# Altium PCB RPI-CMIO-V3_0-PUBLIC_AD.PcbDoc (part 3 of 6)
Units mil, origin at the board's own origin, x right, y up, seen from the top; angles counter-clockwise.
Board outline 3295.4 x 4105.44 mil, 6 copper layers (TOP, GNDT, PWRT, PWRB, GNDB, BOTTOM); 114 components, 152 nets, 703 pads, 476 vias.
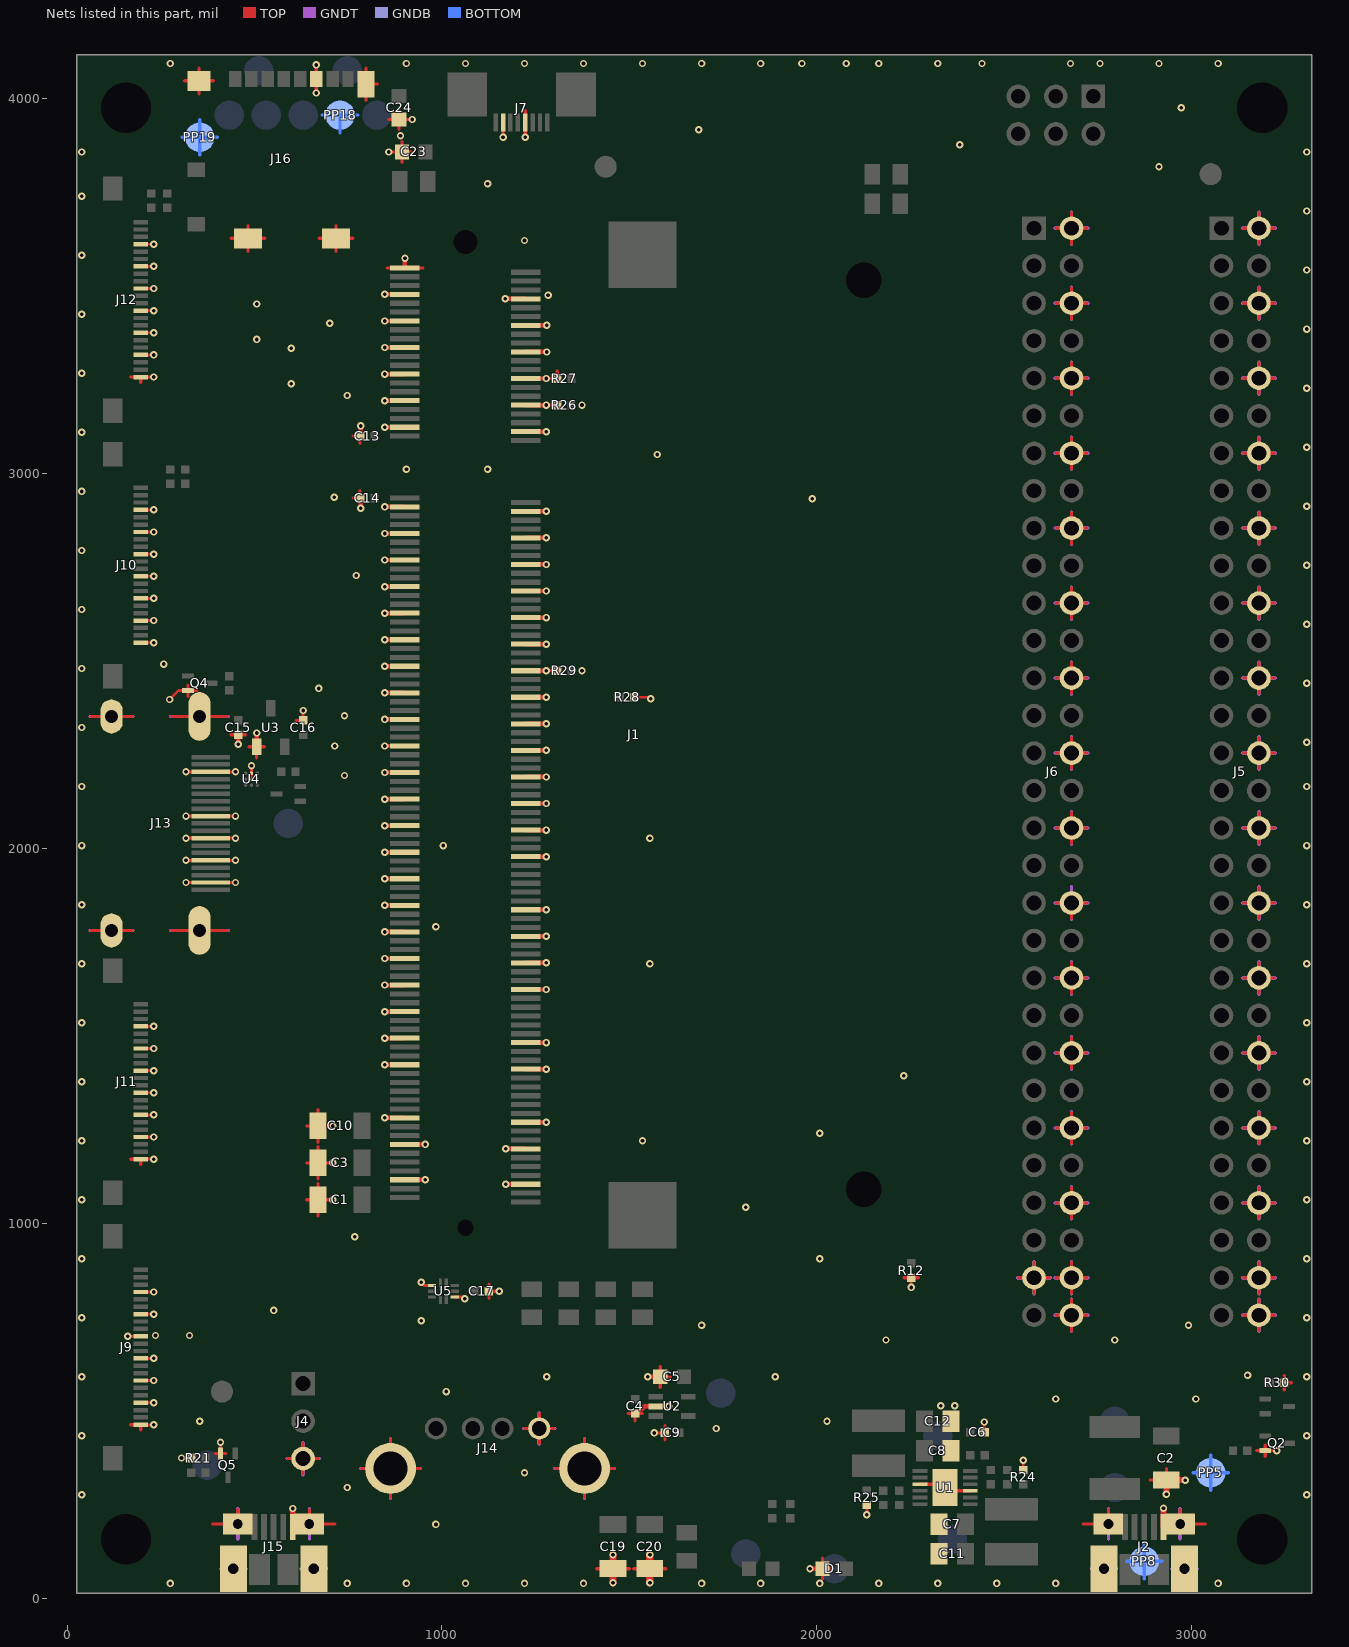
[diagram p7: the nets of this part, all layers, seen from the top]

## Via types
v1: diameter 19.68, hole 9.84, TOP to BOTTOM, 476 vias

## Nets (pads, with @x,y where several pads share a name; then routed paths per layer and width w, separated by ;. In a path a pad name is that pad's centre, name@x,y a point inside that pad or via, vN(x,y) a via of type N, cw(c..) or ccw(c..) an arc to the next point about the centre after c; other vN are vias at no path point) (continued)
GND: C1.2 C2.2 C3.2 C4.2 C5.2 C6.2 C7.2 C8.2 C9.2 C10.2 C11.2 C12.2 C13.2 C14.2 C15.2 C16.2 C17.1 C19.2 C20.2 C23.2 C24.2 D1.1 J1.1 J1.7 J1.8 J1.13 J1.14 J1.19 J1.20 J1.25 J1.26 J1.31 J1.32 J1.37 J1.38 J1.43 J1.44 J1.49 J1.50 J1.55 J1.56 J1.61 J1.62 J1.67 J1.68 J1.73 J1.74 J1.79 J1.80 J1.85 J1.86 J1.91 J1.92 J1.97 J1.98 J1.103 J1.104 J1.109 J1.110 J1.115 J1.116 J1.121 J1.122 J1.127 J1.133 J1.134 J1.139 J1.140 J1.145 J1.146 J1.151 J1.152 J1.157 J1.163 J1.164 J1.169 J1.170 J1.181 J1.182 J1.187 J1.188 J1.195 J1.196 J2.5 J2.6 J2.7 J2.8 J2.9 J4.3 J5.2 J5.6 J5.10 J5.14 J5.18 J5.22 J5.26 J5.30 J5.34 J5.38 J5.42 J5.46 J5.50 J5.54 J5.58 J5.60 J6.2 J6.6 J6.10 J6.14 J6.18 J6.22 J6.26 J6.30 J6.34 J6.38 J6.42 J6.46 J6.50 J6.54 J6.57 J6.58 J6.60 J7.4 J7.7 J9.1 J9.4 J9.7 J9.10 J9.13 J9.16 J9.19 J10.1 J10.4 J10.7 J10.10 J10.13 J10.16 J10.19 J11.1 J11.4 J11.7 J11.10 J11.13 J11.16 J11.19 J12.1 J12.4 J12.7 J12.10 J12.13 J12.16 J12.19 J13.2 J13.5 J13.8 J13.11 J13.17 J13.20 J13.21 J13.22 J13.23 J14.4 J14.5 J14.6 J15.5 J15.6 J15.7 J15.8 J15.9 J16.6 J16.11 J16.12 J16.13 J16.14 PP5.1 PP8.1 PP18.1 PP19.1 Q2.2 Q4.2 Q5.2 R12.1 R21.2 R24.2 R25.2 R26.2 R27.2 R28.2 R29.2 R30.2 U1.3 U1.9 U1.13 U2.2 U3.1 U4.B2 U4.C2 U5.3 U5.8 | length 41875.1
  TOP w7.87: v1(162.32,698.82) J9.13@196.85,698.82 ; J9.1@196.85,462.6 v1(231.38,462.6) ; J9.4@196.85,521.65 v1(231.38,521.65) ; J9.7@196.85,580.71 v1(231.38,580.71) ; J9.10@196.85,639.76 v1(231.38,639.76) ; J9.16@196.85,757.87 v1(231.38,757.87) ; J9.19@196.85,816.93 v1(231.38,816.93) ; J11.1@196.85,1171.26 v1(231.38,1171.26) ; J11.4@196.85,1230.32 v1(231.38,1230.32) ; J11.7@196.85,1289.37 v1(231.38,1289.37) ; J11.10@196.85,1348.43 v1(231.38,1348.43) ; J11.13@196.85,1407.48 v1(231.38,1407.48) ; J11.16@196.85,1466.53 v1(231.38,1466.53) ; J11.19@196.85,1525.59 v1(231.38,1525.59) ; J10.1@196.85,2549.21 v1(231.38,2549.21) ; J10.4@196.85,2608.27 v1(231.38,2608.27) ; J10.7@196.85,2667.32 v1(231.38,2667.32) ; J10.10@196.85,2726.38 v1(231.38,2726.38) ; J10.13@196.85,2785.43 v1(231.38,2785.43) ; J10.16@196.85,2844.49 v1(231.38,2844.49) ; J10.19@196.85,2903.54 v1(231.38,2903.54) ; J12.1@196.85,3257.87 v1(231.38,3257.87) ; J12.4@196.85,3316.93 v1(231.38,3316.93) ; J12.7@196.85,3375.98 v1(231.38,3375.98) ; J12.10@196.85,3435.04 v1(231.38,3435.04) ; J12.13@196.85,3494.09 v1(231.38,3494.09) ; J12.16@196.85,3553.15 v1(231.38,3553.15) ; J12.19@196.85,3612.21 v1(231.38,3612.21) ; v1(273.62,2397.64) 297.24,2421.26 Q4.2@322.84,2421.26 ; v1(305.43,374.02) R21.2@331.3,374.02 R21.2@331.5,374.02 ; v1(317.44,1909.45) J13.2@383.47,1909.45 v1(449.49,1909.45) ; v1(317.44,1968.5) J13.5@383.47,1968.5 v1(449.49,1968.5) ; v1(317.44,2027.56) J13.8@383.47,2027.56 v1(449.49,2027.56) ; v1(317.44,2086.61) J13.11@383.47,2086.61 v1(449.49,2086.61) ; v1(317.44,2204.72) J13.17@383.47,2204.72 v1(449.49,2204.72) ; Q5.2@409.45,385.83 v1(409.45,416.42) ; U4.B2@492.13,2185.04 U4.C2@492.13,2200.79 v1(492.13,2221.14) ; v1(944.88,842.52) 952.76,834.65 U5.3@973.62,834.65 ; U5.8@1034.25,803.15 v1@1061.02,803.15 ; v1(1163.39,3897.64) J7.7@1163.39,3937.01 ; v1(1278.62,2474.41) R29.2@1307.68,2474.41 R29.2@1307.87,2474.41 ; v1(1278.62,3183.07) R26.2@1307.68,3183.07 R26.2@1307.87,3183.07 ; R28.2@1512.99,2403.54 R28.2@1513.19,2403.54 1553.15,2403.54 v1(1557.09,2399.61) ; v1(2133.86,222.76) R25.2@2133.86,248.62 R25.2@2133.86,248.82 ; v1(2251.97,829.06) R12.1@2251.97,854.92 R12.1@2251.97,855.12 ; v1(2446.85,469.96) 2446.85,444.29 C6.2@2448.23,442.91 ; R24.2@2551.18,341.73 R24.2@2551.18,341.93 v1(2551.18,367.8) ; Q2.2@3196.85,393.7 v1(3227.44,393.7)
  TOP w8.46: 63.74,1781.5 J13.21@118.9,1781.5 ; 63.74,2352.36 J13.23@118.9,2352.36 ; J13.21@118.9,1742.09 J13.21@118.9,1781.5 ; J13.21@118.9,1820.91 J13.21@118.9,1781.5 ; J13.23@118.9,2312.95 J13.23@118.9,2352.36 ; J13.23@118.9,2391.77 J13.23@118.9,2352.36 ; 169.25,462.6 J9.1@196.85,462.6 196.85,448.78 ; 169.25,1171.26 J11.1@196.85,1171.26 196.85,1157.44 ; 169.25,3257.87 J12.1@196.85,3257.87 196.85,3244.05 ; 174.06,1781.5 J13.21@118.9,1781.5 ; 174.06,2352.36 J13.23@118.9,2352.36 ; 278.7,1781.5 J13.20@353.54,1781.5 ; 278.7,2352.36 J13.22@353.54,2352.36 ; 313.35,4048.23 J16.12@351.77,4048.23 ; 322.84,2406.46 Q4.2@322.84,2421.26 ; 322.84,2436.06 Q4.2@322.84,2421.26 ; 346.5,2421.26 Q4.2@322.84,2421.26 ; 351.77,4013.74 J16.12@351.77,4048.23 ; 351.77,4082.72 J16.12@351.77,4048.23 ; J13.20@353.54,1742.09 J13.20@353.54,1781.5 ; J13.20@353.54,1820.91 J13.20@353.54,1781.5 ; J13.22@353.54,2312.95 J13.22@353.54,2352.36 ; J13.22@353.54,2391.77 J13.22@353.54,2352.36 ; 387.76,198.03 J15.6@455.71,198.03 455.71,236.46 ; 390.2,4048.23 J16.12@351.77,4048.23 ; 394.65,385.83 Q5.2@409.45,385.83 424.25,385.83 ; 428.39,1781.5 J13.20@353.54,1781.5 ; 428.39,2352.36 J13.22@353.54,2352.36 ; 437.36,2303.74 C15.2@456.69,2303.74 476.02,2303.74 ; 437.36,3627.95 J16.13@482.68,3627.95 ; 482.68,3593.46 J16.13@482.68,3627.95 ; 482.68,3662.44 J16.13@482.68,3627.95 ; 485.2,2271.65 U3.1@505.91,2271.65 ; 505.91,2242.09 U3.1@505.91,2271.65 ; 526.61,2271.65 U3.1@505.91,2271.65 ; 527.99,3627.95 J16.13@482.68,3627.95 ; 588.54,372.44 J4.3@629.92,372.44 ; 610.59,2341.93 C16.2@629.92,2341.93 v1@629.92,2361.06 ; 629.92,331.06 J4.3@629.92,372.44 ; 629.92,413.82 J4.3@629.92,372.44 ; 638.74,1062.99 C1.2@669.29,1062.99 ; 638.74,1161.42 C3.2@669.29,1161.42 ; 638.74,1259.84 C10.2@669.29,1259.84 ; 646.65,236.46 J15.8@646.65,198.03 714.61,198.03 ; v1@665.16,4023.58 J16.6@665.16,4053.15 v1@665.16,4082.72 ; 669.29,1019.65 C1.2@669.29,1062.99 ; 669.29,1106.34 C1.2@669.29,1062.99 ; 669.29,1118.07 C3.2@669.29,1161.42 ; 669.29,1204.76 C3.2@669.29,1161.42 ; 669.29,1216.5 C10.2@669.29,1259.84 ; 669.29,1303.19 C10.2@669.29,1259.84 ; 671.3,372.44 J4.3@629.92,372.44 ; 672.4,3627.95 J16.14@717.72,3627.95 ; v1@699.84,1062.99 C1.2@669.29,1062.99 ; v1@699.84,1161.42 C3.2@669.29,1161.42 ; v1@699.84,1259.84 C10.2@669.29,1259.84 ; 717.72,3593.46 J16.14@717.72,3627.95 ; 717.72,3662.44 J16.14@717.72,3627.95 ; 762.95,2935.04 C14.2@782.09,2935.04 ; 762.95,3100.39 C13.2@782.09,3100.39 ; 763.03,3627.95 J16.14@717.72,3627.95 ; v1@782.09,2915.71 C14.2@782.09,2935.04 ; 782.09,2954.37 C14.2@782.09,2935.04 ; 782.09,3081.06 C13.2@782.09,3100.39 ; v1@782.09,3119.72 C13.2@782.09,3100.39 ; 785.59,346.06 J14.5@863.39,346.06 ; 797.44,3996.02 J16.11@797.44,4039.37 ; 797.44,4082.72 J16.11@797.44,4039.37 ; 828.39,4039.37 J16.11@797.44,4039.37 ; 854.29,3549.21 J1.1@901.58,3549.21 948.86,3549.21 ; 858.23,3944.88 C24.2@885.83,3944.88 ; 863.39,268.27 J14.5@863.39,346.06 ; 863.39,423.86 J14.5@863.39,346.06 ; v1@867.09,3858.27 C23.2@893.7,3858.27 ; 885.83,3918.27 C24.2@885.83,3944.88 ; 885.83,3971.5 C24.2@885.83,3944.88 ; 893.7,3830.67 C23.2@893.7,3858.27 ; 893.7,3885.87 C23.2@893.7,3858.27 ; v1@913.42,3944.88 C24.2@885.83,3944.88 ; 920.32,3858.27 C23.2@893.7,3858.27 ; 941.18,346.06 J14.5@863.39,346.06 ; 1125.39,799.57 C17.1@1125.39,818.9 ; 1125.39,838.23 C17.1@1125.39,818.9 ; v1@1144.53,818.9 C17.1@1125.39,818.9 ; 1220.43,452.76 J14.4@1259.84,452.76 ; v1@1222.44,3905.47 J7.4@1222.44,3937.01 1222.44,3968.54 ; 1259.84,413.35 J14.4@1259.84,452.76 ; 1259.84,492.16 J14.4@1259.84,452.76 ; 1288.54,3253.94 R27.2@1307.68,3253.94 1307.68,3273.27 ; 1299.25,452.76 J14.4@1259.84,452.76 ; 1302.91,346.06 J14.6@1380.71,346.06 ; 1380.71,268.27 J14.6@1380.71,346.06 ; 1380.71,423.86 J14.6@1380.71,346.06 ; 1413.35,78.74 C19.2@1456.69,78.74 1500.04,78.74 ; 1458.5,346.06 J14.6@1380.71,346.06 ; 1496.42,492.72 C4.2@1515.75,492.72 ; 1511.77,78.74 C20.2@1555.12,78.74 1598.47,78.74 ; 1515.75,473.58 C4.2@1515.75,492.72 ; 1535.08,492.72 C4.2@1515.75,492.72 ; v1@1575.95,440.94 C9.2@1595.08,440.94 ; 1582.68,562.95 C5.2@1582.68,590.55 ; 1582.68,618.15 C5.2@1582.68,590.55 ; 1595.08,421.61 C9.2@1595.08,440.94 ; 1595.08,460.28 C9.2@1595.08,440.94 ; 1609.29,590.55 C5.2@1582.68,590.55 ; 2015.75,51.14 D1.1@2015.75,78.74 ; 2015.75,106.34 D1.1@2015.75,78.74 ; 2042.36,78.74 D1.1@2015.75,78.74 ; 2232.64,854.92 R12.1@2251.97,854.92 2271.3,854.92 ; 2538.54,854.72 J6.57@2579.92,854.72 ; 2579.92,813.35 J6.57@2579.92,854.72 ; 2579.92,896.1 J6.57@2579.92,854.72 ; 2621.3,854.72 J6.57@2579.92,854.72 ; 2638.54,754.72 J6.60@2679.92,754.72 ; 2638.54,854.72 J6.58@2679.92,854.72 ; 2638.54,1054.72 J6.54@2679.92,1054.72 ; 2638.54,1254.72 J6.50@2679.92,1254.72 ; 2638.54,1454.72 J6.46@2679.92,1454.72 ; 2638.54,1654.72 J6.42@2679.92,1654.72 ; 2638.54,1854.72 J6.38@2679.92,1854.72 ; 2638.54,2054.72 J6.34@2679.92,2054.72 ; 2638.54,2254.72 J6.30@2679.92,2254.72 ; 2638.54,2454.72 J6.26@2679.92,2454.72 ; 2638.54,2654.72 J6.22@2679.92,2654.72 ; 2638.54,2854.72 J6.18@2679.92,2854.72 ; 2638.54,3054.72 J6.14@2679.92,3054.72 ; 2638.54,3254.72 J6.10@2679.92,3254.72 ; 2638.54,3454.72 J6.6@2679.92,3454.72 ; 2638.54,3654.72 J6.2@2679.92,3654.72 ; 2679.92,713.35 J6.60@2679.92,754.72 ; 2679.92,796.1 J6.60@2679.92,754.72 ; 2679.92,813.35 J6.58@2679.92,854.72 ; 2679.92,896.1 J6.58@2679.92,854.72 ; 2679.92,1013.35 J6.54@2679.92,1054.72 ; 2679.92,1096.1 J6.54@2679.92,1054.72 ; 2679.92,1213.35 J6.50@2679.92,1254.72 ; 2679.92,1296.1 J6.50@2679.92,1254.72 ; 2679.92,1413.35 J6.46@2679.92,1454.72 ; 2679.92,1496.1 J6.46@2679.92,1454.72 ; 2679.92,1613.35 J6.42@2679.92,1654.72 ; 2679.92,1696.1 J6.42@2679.92,1654.72 ; 2679.92,1813.35 J6.38@2679.92,1854.72 ; 2679.92,2013.35 J6.34@2679.92,2054.72 ; 2679.92,2096.1 J6.34@2679.92,2054.72 ; 2679.92,2213.35 J6.30@2679.92,2254.72 ; 2679.92,2296.1 J6.30@2679.92,2254.72 ; 2679.92,2413.35 J6.26@2679.92,2454.72 ; 2679.92,2496.1 J6.26@2679.92,2454.72 ; 2679.92,2613.35 J6.22@2679.92,2654.72 ; 2679.92,2696.1 J6.22@2679.92,2654.72 ; 2679.92,2813.35 J6.18@2679.92,2854.72 ; 2679.92,2896.1 J6.18@2679.92,2854.72 ; 2679.92,3013.35 J6.14@2679.92,3054.72 ; 2679.92,3096.1 J6.14@2679.92,3054.72 ; 2679.92,3213.35 J6.10@2679.92,3254.72 ; 2679.92,3296.1 J6.10@2679.92,3254.72 ; 2679.92,3413.35 J6.6@2679.92,3454.72 ; 2679.92,3496.1 J6.6@2679.92,3454.72 ; 2679.92,3613.35 J6.2@2679.92,3654.72 ; 2679.92,3696.1 J6.2@2679.92,3654.72 ; 2710.59,198.03 J2.6@2778.54,198.03 2778.54,236.46 ; 2721.3,754.72 J6.60@2679.92,754.72 ; 2721.3,854.72 J6.58@2679.92,854.72 ; 2721.3,1054.72 J6.54@2679.92,1054.72 ; 2721.3,1254.72 J6.50@2679.92,1254.72 ; 2721.3,1454.72 J6.46@2679.92,1454.72 ; 2721.3,1654.72 J6.42@2679.92,1654.72 ; 2721.3,1854.72 J6.38@2679.92,1854.72 ; 2721.3,2054.72 J6.34@2679.92,2054.72 ; 2721.3,2254.72 J6.30@2679.92,2254.72 ; 2721.3,2454.72 J6.26@2679.92,2454.72 ; 2721.3,2654.72 J6.22@2679.92,2654.72 ; 2721.3,2854.72 J6.18@2679.92,2854.72 ; 2721.3,3054.72 J6.14@2679.92,3054.72 ; 2721.3,3254.72 J6.10@2679.92,3254.72 ; 2721.3,3454.72 J6.6@2679.92,3454.72 ; 2721.3,3654.72 J6.2@2679.92,3654.72 ; 2889.72,314.96 C2.2@2933.07,314.96 2933.07,345.51 ; 2969.49,236.46 J2.8@2969.49,198.03 3037.44,198.03 ; 3138.54,754.72 J5.60@3179.92,754.72 ; 3138.54,854.72 J5.58@3179.92,854.72 ; 3138.54,1054.72 J5.54@3179.92,1054.72 ; 3138.54,1254.72 J5.50@3179.92,1254.72 ; 3138.54,1454.72 J5.46@3179.92,1454.72 ; 3138.54,1654.72 J5.42@3179.92,1654.72 ; 3138.54,1854.72 J5.38@3179.92,1854.72 ; 3138.54,2054.72 J5.34@3179.92,2054.72 ; 3138.54,2254.72 J5.30@3179.92,2254.72 ; 3138.54,2454.72 J5.26@3179.92,2454.72 ; 3138.54,2654.72 J5.22@3179.92,2654.72 ; 3138.54,2854.72 J5.18@3179.92,2854.72 ; 3138.54,3054.72 J5.14@3179.92,3054.72 ; 3138.54,3254.72 J5.10@3179.92,3254.72 ; 3138.54,3454.72 J5.6@3179.92,3454.72 ; 3138.54,3654.72 J5.2@3179.92,3654.72 ; 3173.19,393.7 Q2.2@3196.85,393.7 ; 3179.92,713.35 J5.60@3179.92,754.72 ; 3179.92,796.1 J5.60@3179.92,754.72 ; 3179.92,813.35 J5.58@3179.92,854.72 ; 3179.92,896.1 J5.58@3179.92,854.72 ; 3179.92,1013.35 J5.54@3179.92,1054.72 ; 3179.92,1096.1 J5.54@3179.92,1054.72 ; 3179.92,1213.35 J5.50@3179.92,1254.72 ; 3179.92,1296.1 J5.50@3179.92,1254.72 ; 3179.92,1413.35 J5.46@3179.92,1454.72 ; 3179.92,1496.1 J5.46@3179.92,1454.72 ; 3179.92,1613.35 J5.42@3179.92,1654.72 ; 3179.92,1696.1 J5.42@3179.92,1654.72 ; 3179.92,1813.35 J5.38@3179.92,1854.72 ; 3179.92,1896.1 J5.38@3179.92,1854.72 ; 3179.92,2013.35 J5.34@3179.92,2054.72 ; 3179.92,2096.1 J5.34@3179.92,2054.72 ; 3179.92,2213.35 J5.30@3179.92,2254.72 ; 3179.92,2296.1 J5.30@3179.92,2254.72 ; 3179.92,2413.35 J5.26@3179.92,2454.72 ; 3179.92,2496.1 J5.26@3179.92,2454.72 ; 3179.92,2613.35 J5.22@3179.92,2654.72 ; 3179.92,2696.1 J5.22@3179.92,2654.72 ; 3179.92,2813.35 J5.18@3179.92,2854.72 ; 3179.92,2896.1 J5.18@3179.92,2854.72 ; 3179.92,3013.35 J5.14@3179.92,3054.72 ; 3179.92,3096.1 J5.14@3179.92,3054.72 ; 3179.92,3213.35 J5.10@3179.92,3254.72 ; 3179.92,3296.1 J5.10@3179.92,3254.72 ; 3179.92,3413.35 J5.6@3179.92,3454.72 ; 3179.92,3496.1 J5.6@3179.92,3454.72 ; 3179.92,3613.35 J5.2@3179.92,3654.72 ; 3179.92,3696.1 J5.2@3179.92,3654.72 ; 3196.85,378.9 Q2.2@3196.85,393.7 ; 3196.85,408.5 Q2.2@3196.85,393.7 ; 3221.3,754.72 J5.60@3179.92,754.72 ; 3221.3,854.72 J5.58@3179.92,854.72 ; 3221.3,1054.72 J5.54@3179.92,1054.72 ; 3221.3,1254.72 J5.50@3179.92,1254.72 ; 3221.3,1454.72 J5.46@3179.92,1454.72 ; 3221.3,1654.72 J5.42@3179.92,1654.72 ; 3221.3,1854.72 J5.38@3179.92,1854.72 ; 3221.3,2054.72 J5.34@3179.92,2054.72 ; 3221.3,2254.72 J5.30@3179.92,2254.72 ; 3221.3,2454.72 J5.26@3179.92,2454.72 ; 3221.3,2654.72 J5.22@3179.92,2654.72 ; 3221.3,2854.72 J5.18@3179.92,2854.72 ; 3221.3,3054.72 J5.14@3179.92,3054.72 ; 3221.3,3254.72 J5.10@3179.92,3254.72 ; 3221.3,3454.72 J5.6@3179.92,3454.72 ; 3221.3,3654.72 J5.2@3179.92,3654.72 ; 3247.44,555.47 R30.2@3247.44,574.8 ; 3247.44,594.13 R30.2@3247.44,574.8 ; 3266.58,574.8 R30.2@3247.44,574.8
  TOP w9.84: U1.3@2275.59,304.13 2333.66,304.13 U1.13@2342.52,295.28 2351.38,286.42 U1.9@2409.45,286.42
  TOP w11.81: v1(456.69,2278.07) C15.2@456.69,2303.74 C15.2@456.69,2305.12 ; U3.1@505.91,2271.65 v1(505.91,2308.15) ; v1(783.47,2907.99) C14.2@783.47,2935.04 ; C13.2@783.47,3100.39 v1(783.47,3127.44) ; v1(847.36,1281.5) J1.181@901.58,1281.5 ; v1(847.36,1423.23) J1.169@901.58,1423.23 ; v1(847.36,1494.09) J1.163@901.58,1494.09 ; v1(847.36,1564.96) J1.157@901.58,1564.96 ; v1(847.36,1635.83) J1.151@901.58,1635.83 ; v1(847.36,1706.69) J1.145@901.58,1706.69 ; v1(847.36,1777.56) J1.139@901.58,1777.56 ; v1(847.36,1848.43) J1.133@901.58,1848.43 ; v1(847.36,1919.29) J1.127@901.58,1919.29 ; v1(847.36,1990.16) J1.121@901.58,1990.16 ; v1(847.36,2061.02) J1.115@901.58,2061.02 ; v1(847.36,2131.89) J1.109@901.58,2131.89 ; v1(847.36,2202.76) J1.103@901.58,2202.76 ; v1(847.36,2273.62) J1.97@901.58,2273.62 ; v1(847.36,2344.49) J1.91@901.58,2344.49 ; v1(847.36,2415.35) J1.85@901.58,2415.35 ; v1(847.36,2486.22) J1.79@901.58,2486.22 ; v1(847.36,2557.09) J1.73@901.58,2557.09 ; v1(847.36,2627.95) J1.67@901.58,2627.95 ; v1(847.36,2698.82) J1.61@901.58,2698.82 ; v1(847.36,2769.68) J1.55@901.58,2769.68 ; v1(847.36,2840.55) J1.49@901.58,2840.55 ; v1(847.36,2911.42) J1.43@901.58,2911.42 ; v1(847.36,3124.02) J1.37@901.58,3124.02 ; v1(847.36,3194.88) J1.31@901.58,3194.88 ; v1(847.36,3265.75) J1.25@901.58,3265.75 ; v1(847.36,3336.61) J1.19@901.58,3336.61 ; v1(847.36,3407.48) J1.13@901.58,3407.48 ; v1(847.36,3478.35) J1.7@901.58,3478.35 ; J1.195@901.58,1116.14 v1(955.79,1116.14) ; J1.187@901.58,1210.63 v1(955.79,1210.63) ; J1.1@901.58,3549.21 v1(901.58,3574.8) ; v1@1167.32,3466.54 v1(1169.29,3466.54) J1.8@1224.41,3466.54 ; v1(1170.2,1104.33) J1.196@1224.41,1104.33 ; v1(1170.2,1198.82) J1.188@1224.41,1198.82 ; J1.182@1224.41,1269.68 v1(1278.62,1269.68) ; J1.170@1224.41,1411.42 v1(1278.62,1411.42) ; J1.164@1224.41,1482.28 v1(1278.62,1482.28) ; J1.152@1224.41,1624.02 v1(1278.62,1624.02) ; J1.146@1224.41,1694.88 v1(1278.62,1694.88) ; J1.140@1224.41,1765.75 v1(1278.62,1765.75) ; J1.134@1224.41,1836.61 v1(1278.62,1836.61) ; J1.122@1224.41,1978.35 v1(1278.62,1978.35) ; J1.116@1224.41,2049.21 v1(1278.62,2049.21) ; J1.110@1224.41,2120.08 v1(1278.62,2120.08) ; J1.104@1224.41,2190.95 v1(1278.62,2190.95) ; J1.98@1224.41,2261.81 v1(1278.62,2261.81) ; J1.92@1224.41,2332.68 v1(1278.62,2332.68) ; J1.86@1224.41,2403.54 v1(1278.62,2403.54) ; J1.80@1224.41,2474.41 v1(1278.62,2474.41) ; J1.74@1224.41,2545.28 v1(1278.62,2545.28) ; J1.68@1224.41,2616.14 v1(1278.62,2616.14) ; J1.62@1224.41,2687.01 v1(1278.62,2687.01) ; J1.56@1224.41,2757.87 v1(1278.62,2757.87) ; J1.50@1224.41,2828.74 v1(1278.62,2828.74) ; J1.44@1224.41,2899.61 v1(1278.62,2899.61) ; J1.38@1224.41,3112.21 v1(1278.62,3112.21) ; J1.32@1224.41,3183.07 v1(1278.62,3183.07) ; J1.26@1224.41,3253.94 v1(1278.62,3253.94) ; J1.20@1224.41,3324.8 v1(1279.53,3324.8) ; J1.14@1224.41,3395.67 v1(1279.53,3395.67) ; C4.2@1515.75,494.09 1523.63,494.09 1541.34,511.81 U2.2@1570.87,511.81 v1(1605.39,511.81) ; v1(1549.13,590.55) C5.2@1582.68,590.55 ; v1(1982.2,78.74) D1.1@2015.75,78.74
  TOP w15.75: J15.5@602.36,189.96 v1(602.36,239.25) ; J2.5@2925.2,189.96 v1(2925.2,240.16) ; v1(2933.07,277.48) C2.2@2933.07,314.96 v1(2983.35,314.96)
  TOP w19.68: v1(1456.69,41.26) C19.2@1456.69,78.74 v1(1456.69,116.22) ; v1(1555.12,41.26) C20.2@1555.12,78.74 v1(1555.12,116.22)
  GNDT w8.46: 61.77,1781.5 J13.21@118.9,1781.5 ; 61.77,2352.36 J13.23@118.9,2352.36 ; J13.21@118.9,1740.12 J13.21@118.9,1781.5 ; J13.21@118.9,1822.87 J13.21@118.9,1781.5 ; J13.23@118.9,2310.98 J13.23@118.9,2352.36 ; J13.23@118.9,2393.74 J13.23@118.9,2352.36 ; 176.02,1781.5 J13.21@118.9,1781.5 ; 176.02,2352.36 J13.23@118.9,2352.36 ; 276.73,1781.5 J13.20@353.54,1781.5 ; 276.73,2352.36 J13.22@353.54,2352.36 ; J13.20@353.54,1740.12 J13.20@353.54,1781.5 ; J13.20@353.54,1822.87 J13.20@353.54,1781.5 ; J13.22@353.54,2310.98 J13.22@353.54,2352.36 ; J13.22@353.54,2393.74 J13.22@353.54,2352.36 ; J15.7@410.39,78.74 J15.7@443.9,78.74 ; J15.6@423.19,198.03 J15.6@455.71,198.03 ; 430.35,1781.5 J13.20@353.54,1781.5 ; 430.35,2352.36 J13.22@353.54,2352.36 ; J15.7@443.9,31.46 J15.7@443.9,78.74 ; J15.7@443.9,126.02 J15.7@443.9,78.74 ; 455.71,157.64 J15.6@455.71,198.03 ; 455.71,238.42 J15.6@455.71,198.03 ; J15.7@477.4,78.74 J15.7@443.9,78.74 ; J15.6@488.23,198.03 J15.6@455.71,198.03 ; 586.58,372.44 J4.3@629.92,372.44 ; J15.8@614.13,198.03 J15.8@646.65,198.03 ; J15.9@624.96,78.74 J15.9@658.47,78.74 ; 629.92,329.09 J4.3@629.92,372.44 ; 629.92,415.79 J4.3@629.92,372.44 ; 646.65,157.64 J15.8@646.65,198.03 ; 646.65,238.42 J15.8@646.65,198.03 ; J15.9@658.47,31.46 J15.9@658.47,78.74 ; J15.9@658.47,126.02 J15.9@658.47,78.74 ; 673.27,372.44 J4.3@629.92,372.44 ; J15.8@679.17,198.03 J15.8@646.65,198.03 ; J15.9@691.97,78.74 J15.9@658.47,78.74 ; 783.62,346.06 J14.5@863.39,346.06 ; 863.39,266.3 J14.5@863.39,346.06 ; 863.39,425.83 J14.5@863.39,346.06 ; 943.15,346.06 J14.5@863.39,346.06 ; 1218.47,452.76 J14.4@1259.84,452.76 ; 1259.84,411.38 J14.4@1259.84,452.76 ; 1259.84,494.13 J14.4@1259.84,452.76 ; 1300.95,346.06 J14.6@1380.71,346.06 ; 1301.22,452.76 J14.4@1259.84,452.76 ; 1380.71,266.3 J14.6@1380.71,346.06 ; 1380.71,425.83 J14.6@1380.71,346.06 ; 1460.47,346.06 J14.6@1380.71,346.06 ; 2536.58,854.72 J6.57@2579.92,854.72 ; 2579.92,811.38 J6.57@2579.92,854.72 ; 2579.92,898.07 J6.57@2579.92,854.72 ; 2623.27,854.72 J6.57@2579.92,854.72 ; 2636.58,754.72 J6.60@2679.92,754.72 ; 2636.58,854.72 J6.58@2679.92,854.72 ; 2636.58,1054.72 J6.54@2679.92,1054.72 ; 2636.58,1254.72 J6.50@2679.92,1254.72 ; 2636.58,1454.72 J6.46@2679.92,1454.72 ; 2636.58,1654.72 J6.42@2679.92,1654.72 ; 2636.58,1854.72 J6.38@2679.92,1854.72 ; 2636.58,2054.72 J6.34@2679.92,2054.72 ; 2636.58,2254.72 J6.30@2679.92,2254.72 ; 2636.58,2454.72 J6.26@2679.92,2454.72 ; 2636.58,2654.72 J6.22@2679.92,2654.72 ; 2636.58,2854.72 J6.18@2679.92,2854.72 ; 2636.58,3054.72 J6.14@2679.92,3054.72 ; 2636.58,3254.72 J6.10@2679.92,3254.72 ; 2636.58,3454.72 J6.6@2679.92,3454.72 ; 2636.58,3654.72 J6.2@2679.92,3654.72 ; 2679.92,711.38 J6.60@2679.92,754.72 ; 2679.92,798.07 J6.60@2679.92,754.72 ; 2679.92,811.38 J6.58@2679.92,854.72 ; 2679.92,898.07 J6.58@2679.92,854.72 ; 2679.92,1011.38 J6.54@2679.92,1054.72 ; 2679.92,1098.07 J6.54@2679.92,1054.72 ; 2679.92,1211.38 J6.50@2679.92,1254.72 ; 2679.92,1298.07 J6.50@2679.92,1254.72 ; 2679.92,1411.38 J6.46@2679.92,1454.72 ; 2679.92,1498.07 J6.46@2679.92,1454.72 ; 2679.92,1611.38 J6.42@2679.92,1654.72 ; 2679.92,1698.07 J6.42@2679.92,1654.72 ; 2679.92,1811.38 J6.38@2679.92,1854.72 ; 2679.92,1898.07 J6.38@2679.92,1854.72 ; 2679.92,2011.38 J6.34@2679.92,2054.72 ; 2679.92,2098.07 J6.34@2679.92,2054.72 ; 2679.92,2211.38 J6.30@2679.92,2254.72 ; 2679.92,2298.07 J6.30@2679.92,2254.72 ; 2679.92,2411.38 J6.26@2679.92,2454.72 ; 2679.92,2498.07 J6.26@2679.92,2454.72 ; 2679.92,2611.38 J6.22@2679.92,2654.72 ; 2679.92,2698.07 J6.22@2679.92,2654.72 ; 2679.92,2811.38 J6.18@2679.92,2854.72 ; 2679.92,2898.07 J6.18@2679.92,2854.72 ; 2679.92,3011.38 J6.14@2679.92,3054.72 ; 2679.92,3098.07 J6.14@2679.92,3054.72 ; 2679.92,3211.38 J6.10@2679.92,3254.72 ; 2679.92,3298.07 J6.10@2679.92,3254.72 ; 2679.92,3411.38 J6.6@2679.92,3454.72 ; 2679.92,3498.07 J6.6@2679.92,3454.72 ; 2679.92,3611.38 J6.2@2679.92,3654.72 ; 2679.92,3698.07 J6.2@2679.92,3654.72 ; 2723.27,754.72 J6.60@2679.92,754.72 ; 2723.27,854.72 J6.58@2679.92,854.72 ; 2723.27,1054.72 J6.54@2679.92,1054.72 ; 2723.27,1254.72 J6.50@2679.92,1254.72 ; 2723.27,1454.72 J6.46@2679.92,1454.72 ; 2723.27,1654.72 J6.42@2679.92,1654.72 ; 2723.27,1854.72 J6.38@2679.92,1854.72 ; 2723.27,2054.72 J6.34@2679.92,2054.72 ; 2723.27,2254.72 J6.30@2679.92,2254.72 ; 2723.27,2454.72 J6.26@2679.92,2454.72 ; 2723.27,2654.72 J6.22@2679.92,2654.72 ; 2723.27,2854.72 J6.18@2679.92,2854.72 ; 2723.27,3054.72 J6.14@2679.92,3054.72 ; 2723.27,3254.72 J6.10@2679.92,3254.72 ; 2723.27,3454.72 J6.6@2679.92,3454.72 ; 2723.27,3654.72 J6.2@2679.92,3654.72 ; J2.7@2733.23,78.74 J2.7@2766.73,78.74 ; J2.6@2746.02,198.03 J2.6@2778.54,198.03 ; J2.7@2766.73,31.46 J2.7@2766.73,78.74 ; J2.7@2766.73,126.02 J2.7@2766.73,78.74 ; 2778.54,157.64 J2.6@2778.54,198.03 ; 2778.54,238.42 J2.6@2778.54,198.03 ; J2.7@2800.24,78.74 J2.7@2766.73,78.74 ; J2.6@2811.06,198.03 J2.6@2778.54,198.03 ; J2.8@2936.97,198.03 J2.8@2969.49,198.03 ; J2.9@2947.8,78.74 J2.9@2981.3,78.74 ; 2969.49,157.64 J2.8@2969.49,198.03 ; 2969.49,238.42 J2.8@2969.49,198.03 ; J2.9@2981.3,31.46 J2.9@2981.3,78.74 ; J2.9@2981.3,126.02 J2.9@2981.3,78.74 ; J2.8@3002.01,198.03 J2.8@2969.49,198.03 ; J2.9@3014.8,78.74 J2.9@2981.3,78.74 ; 3136.58,754.72 J5.60@3179.92,754.72 ; 3136.58,854.72 J5.58@3179.92,854.72 ; 3136.58,1054.72 J5.54@3179.92,1054.72 ; 3136.58,1254.72 J5.50@3179.92,1254.72 ; 3136.58,1454.72 J5.46@3179.92,1454.72 ; 3136.58,1654.72 J5.42@3179.92,1654.72 ; 3136.58,1854.72 J5.38@3179.92,1854.72 ; 3136.58,2054.72 J5.34@3179.92,2054.72 ; 3136.58,2254.72 J5.30@3179.92,2254.72 ; 3136.58,2454.72 J5.26@3179.92,2454.72 ; 3136.58,2654.72 J5.22@3179.92,2654.72 ; 3136.58,2854.72 J5.18@3179.92,2854.72 ; 3136.58,3054.72 J5.14@3179.92,3054.72 ; 3136.58,3254.72 J5.10@3179.92,3254.72 ; 3136.58,3454.72 J5.6@3179.92,3454.72 ; 3136.58,3654.72 J5.2@3179.92,3654.72 ; 3179.92,711.38 J5.60@3179.92,754.72 ; 3179.92,798.07 J5.60@3179.92,754.72 ; 3179.92,811.38 J5.58@3179.92,854.72 ; 3179.92,898.07 J5.58@3179.92,854.72 ; 3179.92,1011.38 J5.54@3179.92,1054.72 ; 3179.92,1098.07 J5.54@3179.92,1054.72 ; 3179.92,1211.38 J5.50@3179.92,1254.72 ; 3179.92,1298.07 J5.50@3179.92,1254.72 ; 3179.92,1411.38 J5.46@3179.92,1454.72 ; 3179.92,1498.07 J5.46@3179.92,1454.72 ; 3179.92,1611.38 J5.42@3179.92,1654.72 ; 3179.92,1698.07 J5.42@3179.92,1654.72 ; 3179.92,1811.38 J5.38@3179.92,1854.72 ; 3179.92,1898.07 J5.38@3179.92,1854.72 ; 3179.92,2011.38 J5.34@3179.92,2054.72 ; 3179.92,2098.07 J5.34@3179.92,2054.72 ; 3179.92,2211.38 J5.30@3179.92,2254.72 ; 3179.92,2298.07 J5.30@3179.92,2254.72 ; 3179.92,2411.38 J5.26@3179.92,2454.72 ; 3179.92,2498.07 J5.26@3179.92,2454.72 ; 3179.92,2611.38 J5.22@3179.92,2654.72 ; 3179.92,2698.07 J5.22@3179.92,2654.72 ; 3179.92,2811.38 J5.18@3179.92,2854.72 ; 3179.92,2898.07 J5.18@3179.92,2854.72 ; 3179.92,3011.38 J5.14@3179.92,3054.72 ; 3179.92,3098.07 J5.14@3179.92,3054.72 ; 3179.92,3211.38 J5.10@3179.92,3254.72 ; 3179.92,3298.07 J5.10@3179.92,3254.72 ; 3179.92,3411.38 J5.6@3179.92,3454.72 ; 3179.92,3498.07 J5.6@3179.92,3454.72 ; 3179.92,3611.38 J5.2@3179.92,3654.72 ; 3179.92,3698.07 J5.2@3179.92,3654.72 ; 3223.27,754.72 J5.60@3179.92,754.72 ; 3223.27,854.72 J5.58@3179.92,854.72 ; 3223.27,1054.72 J5.54@3179.92,1054.72 ; 3223.27,1254.72 J5.50@3179.92,1254.72 ; 3223.27,1454.72 J5.46@3179.92,1454.72 ; 3223.27,1654.72 J5.42@3179.92,1654.72 ; 3223.27,1854.72 J5.38@3179.92,1854.72 ; 3223.27,2054.72 J5.34@3179.92,2054.72 ; 3223.27,2254.72 J5.30@3179.92,2254.72 ; 3223.27,2454.72 J5.26@3179.92,2454.72 ; 3223.27,2654.72 J5.22@3179.92,2654.72 ; 3223.27,2854.72 J5.18@3179.92,2854.72 ; 3223.27,3054.72 J5.14@3179.92,3054.72 ; 3223.27,3254.72 J5.10@3179.92,3254.72 ; 3223.27,3454.72 J5.6@3179.92,3454.72 ; 3223.27,3654.72 J5.2@3179.92,3654.72
  GNDB w8.46: 61.77,1781.5 J13.21@118.9,1781.5 ; 61.77,2352.36 J13.23@118.9,2352.36 ; J13.21@118.9,1740.12 J13.21@118.9,1781.5 ; J13.21@118.9,1822.87 J13.21@118.9,1781.5 ; J13.23@118.9,2310.98 J13.23@118.9,2352.36 ; J13.23@118.9,2393.74 J13.23@118.9,2352.36 ; 176.02,1781.5 J13.21@118.9,1781.5 ; 176.02,2352.36 J13.23@118.9,2352.36 ; 276.73,1781.5 J13.20@353.54,1781.5 ; 276.73,2352.36 J13.22@353.54,2352.36 ; J13.20@353.54,1740.12 J13.20@353.54,1781.5 ; J13.20@353.54,1822.87 J13.20@353.54,1781.5 ; J13.22@353.54,2310.98 J13.22@353.54,2352.36 ; J13.22@353.54,2393.74 J13.22@353.54,2352.36 ; J15.7@410.39,78.74 J15.7@443.9,78.74 ; J15.6@423.19,198.03 J15.6@455.71,198.03 ; 430.35,1781.5 J13.20@353.54,1781.5 ; 430.35,2352.36 J13.22@353.54,2352.36 ; J15.7@443.9,31.46 J15.7@443.9,78.74 ; J15.7@443.9,126.02 J15.7@443.9,78.74 ; 455.71,157.64 J15.6@455.71,198.03 ; 455.71,238.42 J15.6@455.71,198.03 ; J15.7@477.4,78.74 J15.7@443.9,78.74 ; J15.6@488.23,198.03 J15.6@455.71,198.03 ; 586.58,372.44 J4.3@629.92,372.44 ; J15.8@614.13,198.03 J15.8@646.65,198.03 ; J15.9@624.96,78.74 J15.9@658.47,78.74 ; 629.92,329.09 J4.3@629.92,372.44 ; 629.92,415.79 J4.3@629.92,372.44 ; 646.65,157.64 J15.8@646.65,198.03 ; 646.65,238.42 J15.8@646.65,198.03 ; J15.9@658.47,31.46 J15.9@658.47,78.74 ; J15.9@658.47,126.02 J15.9@658.47,78.74 ; 673.27,372.44 J4.3@629.92,372.44 ; J15.8@679.17,198.03 J15.8@646.65,198.03 ; J15.9@691.97,78.74 J15.9@658.47,78.74 ; 783.62,346.06 J14.5@863.39,346.06 ; 863.39,266.3 J14.5@863.39,346.06 ; 863.39,425.83 J14.5@863.39,346.06 ; 943.15,346.06 J14.5@863.39,346.06 ; 1218.47,452.76 J14.4@1259.84,452.76 ; 1259.84,411.38 J14.4@1259.84,452.76 ; 1259.84,494.13 J14.4@1259.84,452.76 ; 1300.95,346.06 J14.6@1380.71,346.06 ; 1301.22,452.76 J14.4@1259.84,452.76 ; 1380.71,266.3 J14.6@1380.71,346.06 ; 1380.71,425.83 J14.6@1380.71,346.06 ; 1460.47,346.06 J14.6@1380.71,346.06 ; 2536.58,854.72 J6.57@2579.92,854.72 ; 2579.92,811.38 J6.57@2579.92,854.72 ; 2579.92,898.07 J6.57@2579.92,854.72 ; 2623.27,854.72 J6.57@2579.92,854.72 ; 2636.58,754.72 J6.60@2679.92,754.72 ; 2636.58,854.72 J6.58@2679.92,854.72 ; 2636.58,1054.72 J6.54@2679.92,1054.72 ; 2636.58,1254.72 J6.50@2679.92,1254.72 ; 2636.58,1454.72 J6.46@2679.92,1454.72 ; 2636.58,1654.72 J6.42@2679.92,1654.72 ; 2636.58,1854.72 J6.38@2679.92,1854.72 ; 2636.58,2054.72 J6.34@2679.92,2054.72 ; 2636.58,2254.72 J6.30@2679.92,2254.72 ; 2636.58,2454.72 J6.26@2679.92,2454.72 ; 2636.58,2654.72 J6.22@2679.92,2654.72 ; 2636.58,2854.72 J6.18@2679.92,2854.72 ; 2636.58,3054.72 J6.14@2679.92,3054.72 ; 2636.58,3254.72 J6.10@2679.92,3254.72 ; 2636.58,3454.72 J6.6@2679.92,3454.72 ; 2636.58,3654.72 J6.2@2679.92,3654.72 ; 2679.92,711.38 J6.60@2679.92,754.72 ; 2679.92,798.07 J6.60@2679.92,754.72 ; 2679.92,811.38 J6.58@2679.92,854.72 ; 2679.92,898.07 J6.58@2679.92,854.72 ; 2679.92,1011.38 J6.54@2679.92,1054.72 ; 2679.92,1098.07 J6.54@2679.92,1054.72 ; 2679.92,1211.38 J6.50@2679.92,1254.72 ; 2679.92,1298.07 J6.50@2679.92,1254.72 ; 2679.92,1411.38 J6.46@2679.92,1454.72 ; 2679.92,1498.07 J6.46@2679.92,1454.72 ; 2679.92,1611.38 J6.42@2679.92,1654.72 ; 2679.92,1698.07 J6.42@2679.92,1654.72 ; 2679.92,1811.38 J6.38@2679.92,1854.72 ; 2679.92,1898.07 J6.38@2679.92,1854.72 ; 2679.92,2011.38 J6.34@2679.92,2054.72 ; 2679.92,2098.07 J6.34@2679.92,2054.72 ; 2679.92,2211.38 J6.30@2679.92,2254.72 ; 2679.92,2298.07 J6.30@2679.92,2254.72 ; 2679.92,2411.38 J6.26@2679.92,2454.72 ; 2679.92,2498.07 J6.26@2679.92,2454.72 ; 2679.92,2611.38 J6.22@2679.92,2654.72 ; 2679.92,2698.07 J6.22@2679.92,2654.72 ; 2679.92,2811.38 J6.18@2679.92,2854.72 ; 2679.92,2898.07 J6.18@2679.92,2854.72 ; 2679.92,3011.38 J6.14@2679.92,3054.72 ; 2679.92,3098.07 J6.14@2679.92,3054.72 ; 2679.92,3211.38 J6.10@2679.92,3254.72 ; 2679.92,3298.07 J6.10@2679.92,3254.72 ; 2679.92,3411.38 J6.6@2679.92,3454.72 ; 2679.92,3498.07 J6.6@2679.92,3454.72 ; 2679.92,3611.38 J6.2@2679.92,3654.72 ; 2679.92,3698.07 J6.2@2679.92,3654.72 ; 2723.27,754.72 J6.60@2679.92,754.72 ; 2723.27,854.72 J6.58@2679.92,854.72 ; 2723.27,1054.72 J6.54@2679.92,1054.72 ; 2723.27,1254.72 J6.50@2679.92,1254.72 ; 2723.27,1454.72 J6.46@2679.92,1454.72 ; 2723.27,1654.72 J6.42@2679.92,1654.72 ; 2723.27,1854.72 J6.38@2679.92,1854.72 ; 2723.27,2054.72 J6.34@2679.92,2054.72 ; 2723.27,2254.72 J6.30@2679.92,2254.72 ; 2723.27,2454.72 J6.26@2679.92,2454.72 ; 2723.27,2654.72 J6.22@2679.92,2654.72 ; 2723.27,2854.72 J6.18@2679.92,2854.72 ; 2723.27,3054.72 J6.14@2679.92,3054.72 ; 2723.27,3254.72 J6.10@2679.92,3254.72 ; 2723.27,3454.72 J6.6@2679.92,3454.72 ; 2723.27,3654.72 J6.2@2679.92,3654.72 ; J2.7@2733.23,78.74 J2.7@2766.73,78.74 ; J2.6@2746.02,198.03 J2.6@2778.54,198.03 ; J2.7@2766.73,31.46 J2.7@2766.73,78.74 ; J2.7@2766.73,126.02 J2.7@2766.73,78.74 ; 2778.54,157.64 J2.6@2778.54,198.03 ; 2778.54,238.42 J2.6@2778.54,198.03 ; J2.7@2800.24,78.74 J2.7@2766.73,78.74 ; J2.6@2811.06,198.03 J2.6@2778.54,198.03 ; J2.8@2936.97,198.03 J2.8@2969.49,198.03 ; J2.9@2947.8,78.74 J2.9@2981.3,78.74 ; 2969.49,157.64 J2.8@2969.49,198.03 ; 2969.49,238.42 J2.8@2969.49,198.03 ; J2.9@2981.3,31.46 J2.9@2981.3,78.74 ; J2.9@2981.3,126.02 J2.9@2981.3,78.74 ; J2.8@3002.01,198.03 J2.8@2969.49,198.03 ; J2.9@3014.8,78.74 J2.9@2981.3,78.74 ; 3136.58,754.72 J5.60@3179.92,754.72 ; 3136.58,854.72 J5.58@3179.92,854.72 ; 3136.58,1054.72 J5.54@3179.92,1054.72 ; 3136.58,1254.72 J5.50@3179.92,1254.72 ; 3136.58,1454.72 J5.46@3179.92,1454.72 ; 3136.58,1654.72 J5.42@3179.92,1654.72 ; 3136.58,1854.72 J5.38@3179.92,1854.72 ; 3136.58,2054.72 J5.34@3179.92,2054.72 ; 3136.58,2254.72 J5.30@3179.92,2254.72 ; 3136.58,2454.72 J5.26@3179.92,2454.72 ; 3136.58,2654.72 J5.22@3179.92,2654.72 ; 3136.58,2854.72 J5.18@3179.92,2854.72 ; 3136.58,3054.72 J5.14@3179.92,3054.72 ; 3136.58,3254.72 J5.10@3179.92,3254.72 ; 3136.58,3454.72 J5.6@3179.92,3454.72 ; 3136.58,3654.72 J5.2@3179.92,3654.72 ; 3179.92,711.38 J5.60@3179.92,754.72 ; 3179.92,798.07 J5.60@3179.92,754.72 ; 3179.92,811.38 J5.58@3179.92,854.72 ; 3179.92,898.07 J5.58@3179.92,854.72 ; 3179.92,1011.38 J5.54@3179.92,1054.72 ; 3179.92,1098.07 J5.54@3179.92,1054.72 ; 3179.92,1211.38 J5.50@3179.92,1254.72 ; 3179.92,1298.07 J5.50@3179.92,1254.72 ; 3179.92,1411.38 J5.46@3179.92,1454.72 ; 3179.92,1498.07 J5.46@3179.92,1454.72 ; 3179.92,1611.38 J5.42@3179.92,1654.72 ; 3179.92,1698.07 J5.42@3179.92,1654.72 ; 3179.92,1811.38 J5.38@3179.92,1854.72 ; 3179.92,1898.07 J5.38@3179.92,1854.72 ; 3179.92,2011.38 J5.34@3179.92,2054.72 ; 3179.92,2098.07 J5.34@3179.92,2054.72 ; 3179.92,2211.38 J5.30@3179.92,2254.72 ; 3179.92,2298.07 J5.30@3179.92,2254.72 ; 3179.92,2411.38 J5.26@3179.92,2454.72 ; 3179.92,2498.07 J5.26@3179.92,2454.72 ; 3179.92,2611.38 J5.22@3179.92,2654.72 ; 3179.92,2698.07 J5.22@3179.92,2654.72 ; 3179.92,2811.38 J5.18@3179.92,2854.72 ; 3179.92,2898.07 J5.18@3179.92,2854.72 ; 3179.92,3011.38 J5.14@3179.92,3054.72 ; 3179.92,3098.07 J5.14@3179.92,3054.72 ; 3179.92,3211.38 J5.10@3179.92,3254.72 ; 3179.92,3298.07 J5.10@3179.92,3254.72 ; 3179.92,3411.38 J5.6@3179.92,3454.72 ; 3179.92,3498.07 J5.6@3179.92,3454.72 ; 3179.92,3611.38 J5.2@3179.92,3654.72 ; 3179.92,3698.07 J5.2@3179.92,3654.72 ; 3223.27,754.72 J5.60@3179.92,754.72 ; 3223.27,854.72 J5.58@3179.92,854.72 ; 3223.27,1054.72 J5.54@3179.92,1054.72 ; 3223.27,1254.72 J5.50@3179.92,1254.72 ; 3223.27,1454.72 J5.46@3179.92,1454.72 ; 3223.27,1654.72 J5.42@3179.92,1654.72 ; 3223.27,1854.72 J5.38@3179.92,1854.72 ; 3223.27,2054.72 J5.34@3179.92,2054.72 ; 3223.27,2254.72 J5.30@3179.92,2254.72 ; 3223.27,2454.72 J5.26@3179.92,2454.72 ; 3223.27,2654.72 J5.22@3179.92,2654.72 ; 3223.27,2854.72 J5.18@3179.92,2854.72 ; 3223.27,3054.72 J5.14@3179.92,3054.72 ; 3223.27,3254.72 J5.10@3179.92,3254.72 ; 3223.27,3454.72 J5.6@3179.92,3454.72 ; 3223.27,3654.72 J5.2@3179.92,3654.72
  BOTTOM w8.46: 63.74,1781.5 J13.21@118.9,1781.5 ; 63.74,2352.36 J13.23@118.9,2352.36 ; J13.21@118.9,1742.09 J13.21@118.9,1781.5 ; J13.21@118.9,1820.91 J13.21@118.9,1781.5 ; J13.23@118.9,2312.95 J13.23@118.9,2352.36 ; J13.23@118.9,2391.77 J13.23@118.9,2352.36 ; 174.06,1781.5 J13.21@118.9,1781.5 ; 174.06,2352.36 J13.23@118.9,2352.36 ; 278.7,1781.5 J13.20@353.54,1781.5 ; 278.7,2352.36 J13.22@353.54,2352.36 ; 307.05,3897.64 PP19.1@354.33,3897.64 ; J13.20@353.54,1742.09 J13.20@353.54,1781.5 ; J13.20@353.54,1820.91 J13.20@353.54,1781.5 ; J13.22@353.54,2312.95 J13.22@353.54,2352.36 ; J13.22@353.54,2391.77 J13.22@353.54,2352.36 ; 354.33,3850.35 PP19.1@354.33,3897.64 ; 354.33,3944.92 PP19.1@354.33,3897.64 ; 401.61,3897.64 PP19.1@354.33,3897.64 ; J15.7@412.36,78.74 J15.7@443.9,78.74 ; J15.6@425.16,198.03 J15.6@455.71,198.03 ; 428.39,1781.5 J13.20@353.54,1781.5 ; 428.39,2352.36 J13.22@353.54,2352.36 ; J15.7@443.9,33.43 J15.7@443.9,78.74 ; J15.7@443.9,124.06 J15.7@443.9,78.74 ; 455.71,159.61 J15.6@455.71,198.03 ; 455.71,236.46 J15.6@455.71,198.03 ; J15.7@475.43,78.74 J15.7@443.9,78.74 ; J15.6@486.26,198.03 J15.6@455.71,198.03 ; 588.54,372.44 J4.3@629.92,372.44 ; J15.8@616.1,198.03 J15.8@646.65,198.03 ; J15.9@626.93,78.74 J15.9@658.47,78.74 ; 629.92,331.06 J4.3@629.92,372.44 ; 629.92,413.82 J4.3@629.92,372.44 ; 646.65,159.61 J15.8@646.65,198.03 ; 646.65,236.46 J15.8@646.65,198.03 ; J15.9@658.47,33.43 J15.9@658.47,78.74 ; J15.9@658.47,124.06 J15.9@658.47,78.74 ; 671.3,372.44 J4.3@629.92,372.44 ; J15.8@677.21,198.03 J15.8@646.65,198.03 ; 681.06,3956.69 PP18.1@728.35,3956.69 ; J15.9@690,78.74 J15.9@658.47,78.74 ; 728.35,3909.41 PP18.1@728.35,3956.69 ; 775.63,3956.69 PP18.1@728.35,3956.69 ; 785.59,346.06 J14.5@863.39,346.06 ; 863.39,268.27 J14.5@863.39,346.06 ; 863.39,423.86 J14.5@863.39,346.06 ; 941.18,346.06 J14.5@863.39,346.06 ; 1220.43,452.76 J14.4@1259.84,452.76 ; 1259.84,413.35 J14.4@1259.84,452.76 ; 1259.84,492.16 J14.4@1259.84,452.76 ; 1299.25,452.76 J14.4@1259.84,452.76 ; 1302.91,346.06 J14.6@1380.71,346.06 ; 1380.71,268.27 J14.6@1380.71,346.06 ; 1380.71,423.86 J14.6@1380.71,346.06 ; 1458.5,346.06 J14.6@1380.71,346.06 ; 2538.54,854.72 J6.57@2579.92,854.72 2621.3,854.72 ; 2638.54,754.72 J6.60@2679.92,754.72 ; 2638.54,854.72 J6.58@2679.92,854.72 2721.3,854.72 ; 2638.54,1054.72 J6.54@2679.92,1054.72 2721.3,1054.72 ; 2638.54,1254.72 J6.50@2679.92,1254.72 2721.3,1254.72 ; 2638.54,1454.72 J6.46@2679.92,1454.72 2721.3,1454.72 ; 2638.54,1654.72 J6.42@2679.92,1654.72 2721.3,1654.72 ; 2638.54,1854.72 J6.38@2679.92,1854.72 2721.3,1854.72 ; 2638.54,2054.72 J6.34@2679.92,2054.72 2721.3,2054.72 ; 2638.54,2254.72 J6.30@2679.92,2254.72 2721.3,2254.72 ; 2638.54,2454.72 J6.26@2679.92,2454.72 2721.3,2454.72 ; 2638.54,2654.72 J6.22@2679.92,2654.72 2721.3,2654.72 ; 2638.54,2854.72 J6.18@2679.92,2854.72 2721.3,2854.72 ; 2638.54,3054.72 J6.14@2679.92,3054.72 2721.3,3054.72 ; 2638.54,3254.72 J6.10@2679.92,3254.72 2721.3,3254.72 ; 2638.54,3454.72 J6.6@2679.92,3454.72 2721.3,3454.72 ; 2638.54,3654.72 J6.2@2679.92,3654.72 ; 2679.92,713.35 J6.60@2679.92,754.72 ; 2679.92,3696.1 J6.2@2679.92,3654.72 ; 2721.3,754.72 J6.60@2679.92,754.72 ; 2721.3,3654.72 J6.2@2679.92,3654.72 ; J2.7@2735.2,78.74 J2.7@2766.73,78.74 ; J2.6@2747.99,198.03 J2.6@2778.54,198.03 ; J2.7@2766.73,33.43 J2.7@2766.73,78.74 ; J2.7@2766.73,124.06 J2.7@2766.73,78.74 ; 2778.54,159.61 J2.6@2778.54,198.03 ; 2778.54,236.46 J2.6@2778.54,198.03 ; J2.7@2798.27,78.74 J2.7@2766.73,78.74 ; J2.6@2809.1,198.03 J2.6@2778.54,198.03 ; 2826.73,98.42 PP8.1@2874.02,98.42 ; 2874.02,51.14 PP8.1@2874.02,98.42 ; 2874.02,145.71 PP8.1@2874.02,98.42 ; 2921.3,98.42 PP8.1@2874.02,98.42 ; J2.8@2938.94,198.03 J2.8@2969.49,198.03 ; J2.9@2949.76,78.74 J2.9@2981.3,78.74 ; 2969.49,159.61 J2.8@2969.49,198.03 ; 2969.49,236.46 J2.8@2969.49,198.03 ; J2.9@2981.3,33.43 J2.9@2981.3,78.74 ; J2.9@2981.3,124.06 J2.9@2981.3,78.74 ; J2.8@3000.04,198.03 J2.8@2969.49,198.03 ; 3003.9,334.65 PP5.1@3051.18,334.65 ; J2.9@3012.84,78.74 J2.9@2981.3,78.74 ; 3051.18,287.36 PP5.1@3051.18,334.65 ; 3051.18,381.93 PP5.1@3051.18,334.65 ; 3098.47,334.65 PP5.1@3051.18,334.65 ; 3138.54,754.72 J5.60@3179.92,754.72 ; 3138.54,854.72 J5.58@3179.92,854.72 ; 3138.54,1054.72 J5.54@3179.92,1054.72 ; 3138.54,1254.72 J5.50@3179.92,1254.72 ; 3138.54,1454.72 J5.46@3179.92,1454.72 ; 3138.54,1654.72 J5.42@3179.92,1654.72 ; 3138.54,1854.72 J5.38@3179.92,1854.72 ; 3138.54,2054.72 J5.34@3179.92,2054.72 ; 3138.54,2254.72 J5.30@3179.92,2254.72 ; 3138.54,2454.72 J5.26@3179.92,2454.72 ; 3138.54,2654.72 J5.22@3179.92,2654.72 ; 3138.54,2854.72 J5.18@3179.92,2854.72 ; 3138.54,3054.72 J5.14@3179.92,3054.72 ; 3138.54,3254.72 J5.10@3179.92,3254.72 ; 3138.54,3454.72 J5.6@3179.92,3454.72 ; 3138.54,3654.72 J5.2@3179.92,3654.72 ; 3179.92,713.35 J5.60@3179.92,754.72 ; 3179.92,796.1 J5.60@3179.92,754.72 ; 3179.92,813.35 J5.58@3179.92,854.72 ; 3179.92,896.1 J5.58@3179.92,854.72 ; 3179.92,1013.35 J5.54@3179.92,1054.72 ; 3179.92,1096.1 J5.54@3179.92,1054.72 ; 3179.92,1213.35 J5.50@3179.92,1254.72 ; 3179.92,1296.1 J5.50@3179.92,1254.72 ; 3179.92,1413.35 J5.46@3179.92,1454.72 ; 3179.92,1496.1 J5.46@3179.92,1454.72 ; 3179.92,1613.35 J5.42@3179.92,1654.72 ; 3179.92,1696.1 J5.42@3179.92,1654.72 ; 3179.92,1813.35 J5.38@3179.92,1854.72 ; 3179.92,1896.1 J5.38@3179.92,1854.72 ; 3179.92,2013.35 J5.34@3179.92,2054.72 ; 3179.92,2096.1 J5.34@3179.92,2054.72 ; 3179.92,2213.35 J5.30@3179.92,2254.72 ; 3179.92,2296.1 J5.30@3179.92,2254.72 ; 3179.92,2413.35 J5.26@3179.92,2454.72 ; 3179.92,2496.1 J5.26@3179.92,2454.72 ; 3179.92,2613.35 J5.22@3179.92,2654.72 ; 3179.92,2696.1 J5.22@3179.92,2654.72 ; 3179.92,2813.35 J5.18@3179.92,2854.72 ; 3179.92,2896.1 J5.18@3179.92,2854.72 ; 3179.92,3013.35 J5.14@3179.92,3054.72 ; 3179.92,3096.1 J5.14@3179.92,3054.72 ; 3179.92,3213.35 J5.10@3179.92,3254.72 ; 3179.92,3296.1 J5.10@3179.92,3254.72 ; 3179.92,3413.35 J5.6@3179.92,3454.72 ; 3179.92,3496.1 J5.6@3179.92,3454.72 ; 3179.92,3613.35 J5.2@3179.92,3654.72 ; 3179.92,3696.1 J5.2@3179.92,3654.72 ; 3221.3,754.72 J5.60@3179.92,754.72 ; 3221.3,854.72 J5.58@3179.92,854.72 ; 3221.3,1054.72 J5.54@3179.92,1054.72 ; 3221.3,1254.72 J5.50@3179.92,1254.72 ; 3221.3,1454.72 J5.46@3179.92,1454.72 ; 3221.3,1654.72 J5.42@3179.92,1654.72 ; 3221.3,1854.72 J5.38@3179.92,1854.72 ; 3221.3,2054.72 J5.34@3179.92,2054.72 ; 3221.3,2254.72 J5.30@3179.92,2254.72 ; 3221.3,2454.72 J5.26@3179.92,2454.72 ; 3221.3,2654.72 J5.22@3179.92,2654.72 ; 3221.3,2854.72 J5.18@3179.92,2854.72 ; 3221.3,3054.72 J5.14@3179.92,3054.72 ; 3221.3,3254.72 J5.10@3179.92,3254.72 ; 3221.3,3454.72 J5.6@3179.92,3454.72 ; 3221.3,3654.72 J5.2@3179.92,3654.72
  other v1: 275.59,39.37 748.03,39.37 905.51,39.37 1062.99,39.37 1220.47,39.37 1377.95,39.37 1692.91,39.37 1850.39,39.37 2007.87,39.37 2165.35,39.37 2322.84,39.37 2480.32,39.37 2637.8,39.37 3070.87,39.37 984.25,196.85 39.37,275.59 3307.09,275.59 748.03,295.28 1220.47,334.65 39.37,433.07 3307.09,433.07 1566.93,440.94 1732.28,452.76 354.33,472.44 2027.56,472.44 2330.71,513.78 2368.11,513.78 2637.8,531.5 3011.81,531.5 1011.81,551.18 39.37,590.55 1279.53,590.55 1889.76,590.55 3307.09,590.55 3149.61,594.49 2185.04,688.98 2795.28,688.98 236.22,700.79 326.77,700.79 1692.91,728.35 2992.13,728.35 944.88,740.16 39.37,748.03 3307.09,748.03 551.18,767.72 1061.02,799.21 1153.54,818.9 39.37,905.51 2007.87,905.51 3307.09,905.51 767.72,964.57 1811.02,1043.31 39.37,1062.99 708.66,1062.99 3307.09,1062.99 708.66,1161.42 39.37,1220.47 1535.43,1220.47 3307.09,1220.47 2007.87,1240.16 708.66,1259.84 39.37,1377.95 3307.09,1377.95 2232.28,1393.7 39.37,1535.43 3307.09,1535.43 39.37,1692.91 1555.12,1692.91 3307.09,1692.91 984.25,1791.34 39.37,1850.39 3307.09,1850.39 39.37,2007.87 1003.94,2007.87 3307.09,2007.87 1555.12,2027.56 39.37,2165.35 3307.09,2165.35 740.16,2194.88 714.57,2273.62 3307.09,2283.47 39.37,2322.84 740.16,2354.33 629.92,2368.11 671.26,2427.16 3307.09,2440.95 1374.02,2474.41 39.37,2480.32 257.87,2492.13 3307.09,2598.43 39.37,2637.8 771.65,2728.35 3307.09,2755.91 39.37,2795.28 3307.09,2913.39 1988.19,2933.07 712.6,2937.01 39.37,2952.76 905.51,3011.81 1122.05,3011.81 1574.8,3051.18 3307.09,3070.87 39.37,3110.24 1374.02,3183.07 748.03,3208.66 3307.09,3228.35 598.42,3240.16 39.37,3267.72 598.42,3334.65 505.91,3358.27 3307.09,3385.83 700.79,3401.58 39.37,3425.2 505.91,3452.76 1283.47,3476.38 3307.09,3543.31 39.37,3582.68 1220.47,3622.05 3307.09,3700.79 39.37,3740.16 1122.05,3773.62 2913.39,3818.9 39.37,3858.27 858.27,3858.27 3307.09,3858.27 2381.89,3877.95 1222.44,3897.64 889.76,3901.58 1685.04,3917.32 921.26,3944.88 2972.44,3976.38 665.35,4015.75 665.35,4090.55 275.59,4094.49 905.51,4094.49 1062.99,4094.49 1220.47,4094.49 1377.95,4094.49 1535.43,4094.49 1692.91,4094.49 1850.39,4094.49 1960.63,4094.49 2078.74,4094.49 2165.35,4094.49 2322.84,4094.49 2440.95,4094.49 2677.16,4094.49 2755.91,4094.49 2913.39,4094.49 3070.87,4094.49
